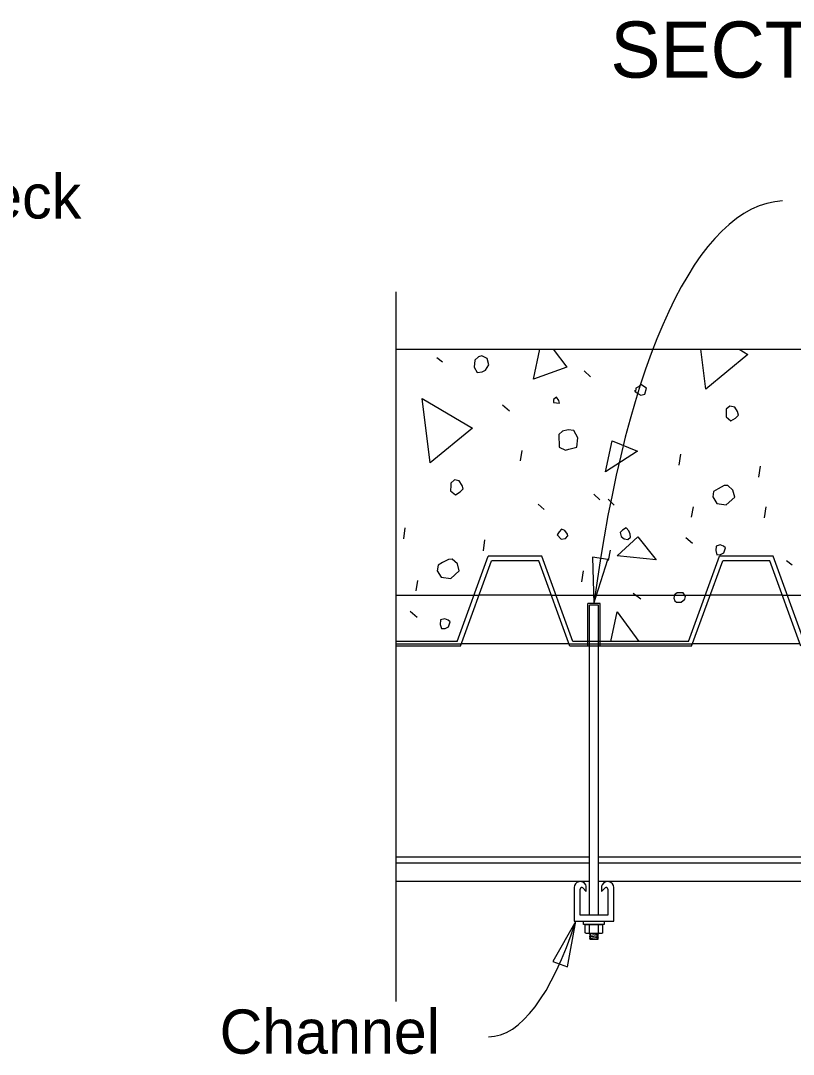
# Model space of a CAD drawing. Extents: x 0 to 30.8, y 0 to 21.2.
# Drawn here: x 12.468 to 15.11, y 6.124 to 9.659 of the extents above; entities that cross this region are included whole.
import ezdxf

# ---------------------------------------------------------------- set-up
doc = ezdxf.new("R2010")
doc.units = 0
for name, color, linetype in [('Dimension', 7, 'Continuous'), ('Lighting', 7, 'Continuous'), ('Miscellaneous', 7, 'Continuous'), ('SteelGirder', 7, 'Continuous'), ('SteelGirder_h', 7, 'Continuous'), ('SupstrConc', 7, 'Continuous'), ('TextStructures', 7, 'Continuous')]:
    doc.layers.add(name, color=color, linetype=linetype)

msp = doc.modelspace()

# ---------------------------------------------------------------- linework, layer by layer
at = {"layer": 'Dimension'}
msp.add_lwpolyline([(13.7516, 6.3039), (13.7516, 8.7314)], dxfattribs=at)
for points in [[(14.4281, 7.6655), (14.4759, 7.8165), (14.4235, 7.8238)], [(14.3657, 6.5793), (14.2875, 6.4415), (14.3372, 6.4234)]]:
    msp.add_lwpolyline(points, close=True, dxfattribs=at)
for centre, major_axis, ratio, start_param, end_param in [((15.2306, 6.1243), (0.1574, -2.9184), 0.2923, 3.141622, 4.140363), ((14.0547, 7.8515), (-0.0129, 1.6676), 0.280094, 3.141615, 3.84244)]:
    msp.add_ellipse(centre, major_axis=major_axis, ratio=ratio, start_param=start_param, end_param=end_param, dxfattribs=at)
at = {"layer": 'Lighting'}
for p, q in [((14.4126, 6.798), (13.7516, 6.798)), ((15.199, 6.798), (14.4438, 6.798)), ((14.4126, 6.7772), (13.7516, 6.7772)), ((15.2293, 6.7772), (14.4438, 6.7772)), ((14.4126, 6.7147), (13.7516, 6.7147)), ((14.3605, 6.6939), (14.3605, 6.5793)), ((14.3813, 6.6001), (14.3813, 6.6891)), ((14.3901, 6.6928), (14.4021, 6.6808)), ((14.4021, 6.6987), (14.3999, 6.7031)), ((14.4021, 6.6808), (14.4021, 6.6987)), ((16.3605, 6.7147), (14.4438, 6.7147)), ((14.4564, 6.7031), (14.4543, 6.6987)), ((14.4543, 6.6987), (14.4543, 6.6808)), ((14.4543, 6.6808), (14.4662, 6.6928)), ((14.4751, 6.6891), (14.4751, 6.6001)), ((14.4959, 6.5793), (14.4959, 6.6939)), ((14.3605, 6.5793), (14.4959, 6.5793)), ((14.4751, 6.6001), (14.3813, 6.6001))]:
    msp.add_line(p, q, dxfattribs=at)
for centre, radius, start, end in [((14.3813, 6.6939), 0.0208, 26.1794, 179.9999), ((14.3865, 6.6891), 0.0052, 45, 180), ((14.4751, 6.6939), 0.0208, 0.0001, 153.8206), ((14.4699, 6.6891), 0.0052, 360, 135)]:
    msp.add_arc(centre, radius, start, end, dxfattribs=at)
at = {"layer": 'Miscellaneous'}
for p, q in [((13.8911, 8.507), (13.9107, 8.4916)), ((14.3952, 8.4609), (14.4161, 8.4407)), ((14.1157, 8.3446), (14.1391, 8.325)), ((14.1772, 8.154), (14.1832, 8.1893)), ((14.7196, 8.1389), (14.725, 8.1766)), ((14.9919, 8.098), (14.9974, 8.1357)), ((14.4277, 8.04), (14.4487, 8.0197)), ((14.2379, 8.0047), (14.2582, 7.9868)), ((14.4765, 8.022), (14.4975, 8.0018)), ((14.762, 7.9613), (14.768, 7.9966)), ((15.0113, 7.9583), (15.0167, 7.9959)), ((13.7778, 7.8866), (13.7832, 7.9243)), ((14.0502, 7.8457), (14.0556, 7.8834)), ((14.7419, 7.8913), (14.7653, 7.8716)), ((14.4782, 7.8128), (14.4843, 7.8481)), ((13.9607, 7.5353), (14.0669, 7.827)), ((14.2502, 7.827), (14.0669, 7.827)), ((14.3564, 7.5353), (14.2502, 7.827)), ((14.7512, 7.5353), (14.8574, 7.827)), ((15.0407, 7.827), (14.8574, 7.827)), ((15.1469, 7.5353), (15.0407, 7.827)), ((15.0865, 7.8128), (15.1061, 7.7973)), ((13.9717, 7.5197), (14.0779, 7.8114)), ((14.2393, 7.8114), (14.0779, 7.8114)), ((14.3455, 7.5197), (14.2393, 7.8114)), ((14.7621, 7.5197), (14.8683, 7.8114)), ((15.0297, 7.8114), (14.8683, 7.8114)), ((15.1359, 7.5197), (15.0297, 7.8114)), ((13.8202, 7.709), (13.8263, 7.7443)), ((14.3867, 7.7391), (14.3921, 7.7768)), ((14.5626, 7.7009), (14.5884, 7.6819)), ((13.8001, 7.6389), (13.8235, 7.6193)), ((13.9607, 7.5353), (13.7516, 7.5353)), ((14.7512, 7.5353), (14.3564, 7.5353)), ((13.9717, 7.5197), (13.7516, 7.5197)), ((14.7621, 7.5197), (14.3455, 7.5197))]:
    msp.add_line(p, q, dxfattribs=at)
for points in [[(14.2216, 8.4325), (14.2434, 8.5353)], [(14.2891, 8.5353), (14.3349, 8.4733), (14.2216, 8.4325)], [(14.8104, 8.3988), (14.7931, 8.5353)], [(14.9245, 8.5353), (14.9545, 8.5176), (14.8104, 8.3988)], [(14.0204, 8.4977), (14.019, 8.474), (14.029, 8.456), (14.0465, 8.4581), (14.0579, 8.4637), (14.0686, 8.4821), (14.0627, 8.5038), (14.045, 8.512), (14.0329, 8.5088), (14.0204, 8.4977)], [(14.5698, 8.3887), (14.5882, 8.3781), (14.6027, 8.3819), (14.6078, 8.4014), (14.5888, 8.4145), (14.5804, 8.407), (14.5714, 8.402), (14.5698, 8.3887), (14.5685, 8.3935)], [(13.8686, 8.1464), (13.8407, 8.3667), (14.0128, 8.2653), (13.8686, 8.1464)], [(14.2897, 8.3524), (14.3109, 8.3504), (14.3083, 8.36), (14.3003, 8.3708), (14.2895, 8.3627), (14.2897, 8.3524)], [(14.8802, 8.3217), (14.8799, 8.3035), (14.8965, 8.2899), (14.9121, 8.2992), (14.9223, 8.3097), (14.919, 8.3218), (14.9097, 8.3374), (14.8932, 8.3407), (14.8807, 8.3296), (14.8802, 8.3217)], [(14.3085, 8.2436), (14.3098, 8.1999), (14.3306, 8.19), (14.3427, 8.1932), (14.3692, 8.2003), (14.3735, 8.2325), (14.3592, 8.2572), (14.3403, 8.2599), (14.321, 8.2547), (14.3085, 8.2436)], [(14.4671, 8.1153), (14.4901, 8.2224), (14.5775, 8.1863), (14.4671, 8.1153)], [(13.9384, 8.0694), (13.9381, 8.0512), (13.9547, 8.0375), (13.9704, 8.0469), (13.9805, 8.0573), (13.9773, 8.0694), (13.9679, 8.085), (13.9515, 8.0884), (13.9389, 8.0773), (13.9384, 8.0694)], [(14.8342, 8.0299), (14.8479, 8.0077), (14.8801, 8.0034), (14.9094, 8.0293), (14.9029, 8.0535), (14.8857, 8.0695), (14.873, 8.0687), (14.8525, 8.0581), (14.8369, 8.0487), (14.8342, 8.0299)], [(14.3021, 7.9002), (14.3163, 7.8859), (14.3314, 7.8874), (14.3392, 7.8972), (14.3379, 7.9021), (14.3291, 7.9152), (14.3175, 7.9199), (14.3098, 7.9101), (14.3021, 7.9002)], [(14.5211, 7.8942), (14.531, 7.8865), (14.5443, 7.8849), (14.5527, 7.8923), (14.5525, 7.9026), (14.5469, 7.9141), (14.5388, 7.9248), (14.5256, 7.9161), (14.5173, 7.9087), (14.5211, 7.8942)], [(14.5077, 7.8285), (14.5781, 7.894), (14.6407, 7.815), (14.5077, 7.8285)], [(14.8446, 7.8463), (14.8484, 7.8318), (14.8612, 7.8326), (14.8726, 7.8383), (14.8784, 7.8554), (14.8716, 7.8613), (14.86, 7.866), (14.8455, 7.8621), (14.8446, 7.8463)], [(13.8924, 7.7775), (13.9061, 7.7553), (13.9383, 7.751), (13.9676, 7.777), (13.9612, 7.8011), (13.9439, 7.8172), (13.9312, 7.8164), (13.9107, 7.8057), (13.8951, 7.7964), (13.8924, 7.7775)], [(14.7043, 7.6741), (14.7105, 7.6706), (14.7262, 7.6697), (14.7388, 7.6808), (14.7417, 7.6893), (14.733, 7.7025), (14.7124, 7.7022), (14.704, 7.6948), (14.7017, 7.6838), (14.7043, 7.6741)], [(14.4857, 7.5353), (14.5073, 7.6369), (14.5822, 7.5353)], [(13.9028, 7.5939), (13.9067, 7.5795), (13.9194, 7.5803), (13.9308, 7.5859), (13.9366, 7.603), (13.9298, 7.609), (13.9182, 7.6136), (13.9037, 7.6097), (13.9028, 7.5939)]]:
    msp.add_lwpolyline(points, dxfattribs=at)
at = {"layer": 'SteelGirder'}
for p, q in [((14.282, 7.694), (14.0351, 7.694)), ((15.0725, 7.694), (14.8256, 7.694)), ((14.449, 7.6655), (14.4074, 7.6655)), ((14.4074, 7.5197), (14.4074, 7.6655)), ((14.4126, 6.6001), (14.4126, 7.6603)), ((14.4438, 7.6603), (14.4126, 7.6603)), ((14.4438, 6.6001), (14.4438, 7.6603)), ((14.449, 7.5197), (14.449, 7.6655)), ((14.3427, 7.5273), (13.9744, 7.5273)), ((15.1332, 7.5273), (14.7649, 7.5273)), ((14.3981, 6.5398), (14.3981, 6.5682)), ((14.3981, 6.5682), (14.4582, 6.5682)), ((14.4131, 6.5398), (14.4131, 6.5682)), ((14.4432, 6.5398), (14.4432, 6.5682)), ((14.4582, 6.5398), (14.4582, 6.5682)), ((14.4056, 6.5376), (14.4507, 6.5376)), ((14.4125, 6.537), (14.4191, 6.5376)), ((14.4125, 6.537), (14.4135, 6.5376)), ((14.4177, 6.5348), (14.4125, 6.537)), ((14.4125, 6.5318), (14.4177, 6.5348)), ((14.4125, 6.5318), (14.4437, 6.5345)), ((14.4177, 6.5296), (14.4125, 6.5318)), ((14.4125, 6.5266), (14.4177, 6.5296)), ((14.4125, 6.5266), (14.4437, 6.5293)), ((14.4177, 6.5244), (14.4125, 6.5266)), ((14.4125, 6.5214), (14.4177, 6.5244)), ((14.4125, 6.5214), (14.4437, 6.5241)), ((14.4177, 6.5192), (14.4125, 6.5214)), ((14.4143, 6.5173), (14.4177, 6.5192)), ((14.4143, 6.5173), (14.4409, 6.5173)), ((14.4244, 6.5173), (14.4437, 6.5189)), ((14.4385, 6.5366), (14.4401, 6.5376)), ((14.4437, 6.5345), (14.4385, 6.5366)), ((14.4385, 6.5314), (14.4437, 6.5345)), ((14.4437, 6.5293), (14.4385, 6.5314)), ((14.4385, 6.5263), (14.4437, 6.5293)), ((14.4437, 6.5241), (14.4385, 6.5263)), ((14.4385, 6.521), (14.4437, 6.5241)), ((14.4437, 6.5189), (14.4385, 6.521)), ((14.4409, 6.5173), (14.4437, 6.5189))]:
    msp.add_line(p, q, dxfattribs=at)
msp.add_lwpolyline([(14.4634, 6.5793), (14.4634, 6.5682), (14.3929, 6.5682), (14.3929, 6.5793)], close=True, dxfattribs=at)
for centre, radius, start, end in [((14.4056, 6.5514), 0.0138, 236.9791, 303.0209), ((14.4281, 6.5894), 0.0519, 253.1396, 286.8604), ((14.4507, 6.5514), 0.0138, 236.9791, 303.0209)]:
    msp.add_arc(centre, radius, start, end, dxfattribs=at)
at = {"layer": 'SteelGirder_h'}
for p, q in [((13.7516, 7.694), (14.0351, 7.694)), ((14.282, 7.694), (14.8256, 7.694)), ((15.0725, 7.694), (15.616, 7.694)), ((13.7516, 7.5273), (13.9744, 7.5273)), ((14.3427, 7.5273), (14.7649, 7.5273))]:
    msp.add_line(p, q, dxfattribs=at)
at = {"layer": 'SupstrConc'}
msp.add_line((13.7516, 8.5353), (20.7608, 8.5353), dxfattribs=at)

# ---------------------------------------------------------------- texts
at = {"layer": 'TextStructures'}
for s, height, p in [('SECTION A-A', 0.192, (14.4844, 9.4639)), ('Bridge Deck', 0.1512, (11.5739, 8.9822)), ('Channel', 0.1512, (13.1483, 6.1259))]:
    msp.add_text(s, height=height, dxfattribs=at).set_placement(p)

doc.saveas('drawing.dxf')
